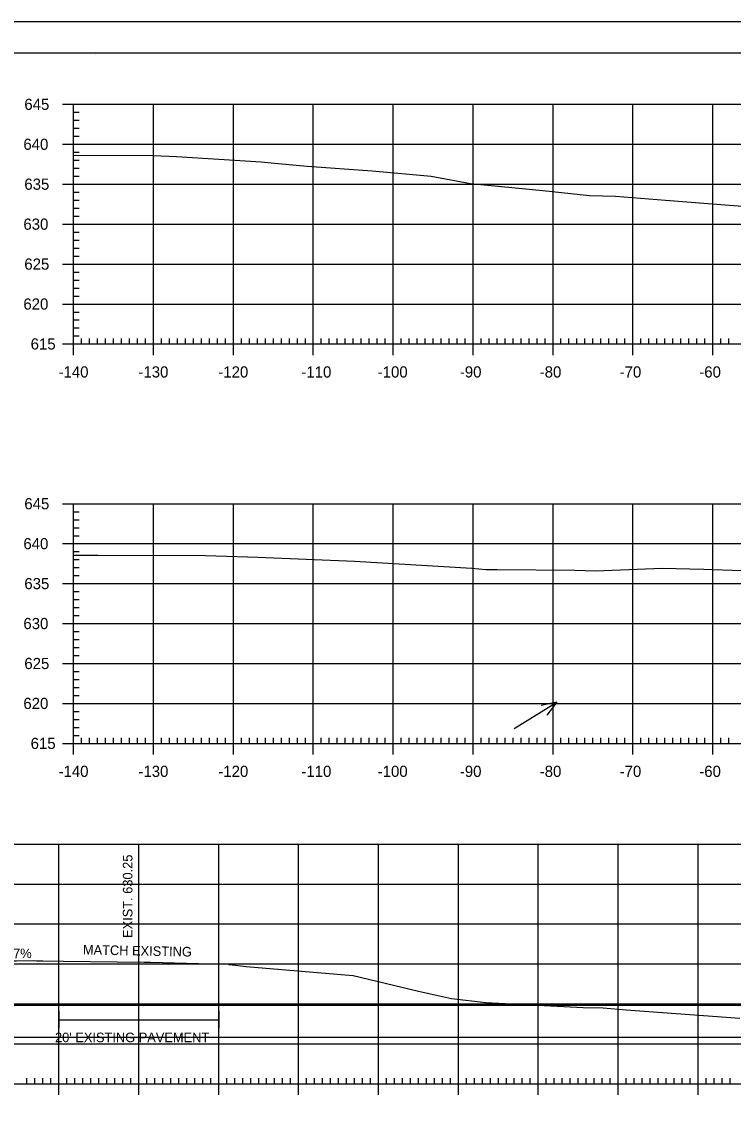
# Model space of a CAD drawing. Extents: x 1381471 to 1382703, y 370300 to 371487.
# Drawn here: x 1381990.1 to 1382079.2, y 370412.6 to 370547.6 of the extents above; entities that cross this region are included whole.
import ezdxf

# ---------------------------------------------------------------- set-up
doc = ezdxf.new("R2010")
doc.units = 0
for name, color, linetype in [('Level 16', 7, 'Continuous'), ('Level 18', 7, 'Continuous'), ('Level 21', 7, 'Continuous'), ('Level 22', 7, 'Continuous'), ('Level 26', 7, 'Continuous'), ('Level 4', 7, 'Continuous'), ('Level 40', 7, 'Continuous'), ('Level 41', 7, 'Continuous'), ('Level 42', 7, 'Continuous'), ('Level 45', 7, 'Continuous'), ('Level 6', 7, 'Continuous')]:
    doc.layers.add(name, color=color, linetype=linetype)

msp = doc.modelspace()

# ---------------------------------------------------------------- linework, layer by layer
at = {"layer": 'Level 16'}
for p, q in [((1381994.77, 370423.74), (1381994.77, 370421.61)), ((1382014.77, 370423.74), (1382014.77, 370421.61)), ((1381994.77, 370422.68), (1382014.77, 370422.68))]:
    msp.add_line(p, q, dxfattribs=at)
msp.add_lwpolyline([(1381986.4, 370430.03), (1381991.53, 370430.07), (1381991.98, 370430.06), (1381992.77, 370430.05)], dxfattribs=at)
at = {"layer": 'Level 18'}
msp.add_lwpolyline([(1381987.42, 370430.02), (1381991.53, 370430.07), (1381991.98, 370430.06), (1382005.44, 370429.9), (1382006.23, 370429.88), (1382012.23, 370429.71), (1382016, 370429.61), (1382016.04, 370429.6), (1382016.11, 370429.59), (1382018.19, 370429.34), (1382031.61, 370428.19), (1382039.79, 370426.26), (1382043.91, 370425.34), (1382048.19, 370424.85), (1382060.4, 370424.19), (1382062.89, 370424.17), (1382065.76, 370423.9), (1382080, 370422.87)], dxfattribs=at)
at = {"layer": 'Level 22'}
for p, q in [((1381864.77, 370444.66), (1382144.77, 370444.66)), ((1381994.77, 370414.66), (1381994.77, 370444.66)), ((1382004.77, 370414.66), (1382004.77, 370444.66)), ((1382014.77, 370414.66), (1382014.77, 370444.66)), ((1382024.77, 370414.66), (1382024.77, 370444.66)), ((1382034.77, 370414.66), (1382034.77, 370444.66)), ((1382044.77, 370414.66), (1382044.77, 370444.66)), ((1382054.77, 370414.66), (1382054.77, 370444.66)), ((1382064.77, 370414.66), (1382064.77, 370444.66)), ((1382074.77, 370414.66), (1382074.77, 370444.66)), ((1381864.77, 370439.66), (1382144.77, 370439.66)), ((1381864.77, 370434.66), (1382144.77, 370434.66)), ((1381864.77, 370429.66), (1382144.77, 370429.66)), ((1381864.77, 370424.66), (1382144.77, 370424.66)), ((1381864.77, 370419.66), (1382144.77, 370419.66)), ((1381864.77, 370414.66), (1382144.77, 370414.66))]:
    msp.add_line(p, q, dxfattribs=at)
at = {"layer": 'Level 26'}
msp.add_line((1381834.37, 370547.63), (1382167.7, 370547.63), dxfattribs=at)
for points in [[(1381834.36, 370547.63), (1382167.7, 370547.63), (1382167.7, 370334.29), (1381834.36, 370334.29)], [(1382080.69, 370543.73), (1382100.31, 370543.73), (1382100.31, 370533.85), (1382116.42, 370533.85), (1382139.62, 370533.85), (1382139.62, 370501.18), (1382162.83, 370501.18), (1382162.95, 370338.27), (1381846.77, 370338.27), (1381846.77, 370543.73)]]:
    msp.add_lwpolyline(points, close=True, dxfattribs=at)
at = {"layer": 'Level 4'}
for p, q in [((1381994.77, 370413.26), (1381994.77, 370416.06)), ((1382004.77, 370413.26), (1382004.77, 370416.06)), ((1382014.77, 370413.26), (1382014.77, 370416.06)), ((1382024.77, 370413.26), (1382024.77, 370416.06)), ((1382034.77, 370413.26), (1382034.77, 370416.06)), ((1382044.77, 370413.26), (1382044.77, 370416.06)), ((1382054.77, 370413.26), (1382054.77, 370416.06)), ((1382064.77, 370413.26), (1382064.77, 370416.06)), ((1382074.77, 370413.26), (1382074.77, 370416.06)), ((1381864.77, 370414.66), (1382144.77, 370414.66)), ((1381990.77, 370414.66), (1381990.77, 370415.36)), ((1381991.77, 370414.66), (1381991.77, 370415.36)), ((1381992.77, 370414.66), (1381992.77, 370415.36)), ((1381993.77, 370414.66), (1381993.77, 370415.36)), ((1381995.77, 370414.66), (1381995.77, 370415.36)), ((1381996.77, 370414.66), (1381996.77, 370415.36)), ((1381997.77, 370414.66), (1381997.77, 370415.36)), ((1381998.77, 370414.66), (1381998.77, 370415.36)), ((1381999.77, 370414.66), (1381999.77, 370415.36)), ((1382000.77, 370414.66), (1382000.77, 370415.36)), ((1382001.77, 370414.66), (1382001.77, 370415.36)), ((1382002.77, 370414.66), (1382002.77, 370415.36)), ((1382003.77, 370414.66), (1382003.77, 370415.36)), ((1382005.77, 370414.66), (1382005.77, 370415.36)), ((1382006.77, 370414.66), (1382006.77, 370415.36)), ((1382007.77, 370414.66), (1382007.77, 370415.36)), ((1382008.77, 370414.66), (1382008.77, 370415.36)), ((1382009.77, 370414.66), (1382009.77, 370415.36)), ((1382010.77, 370414.66), (1382010.77, 370415.36)), ((1382011.77, 370414.66), (1382011.77, 370415.36)), ((1382012.77, 370414.66), (1382012.77, 370415.36)), ((1382013.77, 370414.66), (1382013.77, 370415.36)), ((1382015.77, 370414.66), (1382015.77, 370415.36)), ((1382016.77, 370414.66), (1382016.77, 370415.36)), ((1382017.77, 370414.66), (1382017.77, 370415.36)), ((1382018.77, 370414.66), (1382018.77, 370415.36)), ((1382019.77, 370414.66), (1382019.77, 370415.36)), ((1382020.77, 370414.66), (1382020.77, 370415.36)), ((1382021.77, 370414.66), (1382021.77, 370415.36)), ((1382022.77, 370414.66), (1382022.77, 370415.36)), ((1382023.77, 370414.66), (1382023.77, 370415.36)), ((1382025.77, 370414.66), (1382025.77, 370415.36)), ((1382026.77, 370414.66), (1382026.77, 370415.36)), ((1382027.77, 370414.66), (1382027.77, 370415.36)), ((1382028.77, 370414.66), (1382028.77, 370415.36)), ((1382029.77, 370414.66), (1382029.77, 370415.36)), ((1382030.77, 370414.66), (1382030.77, 370415.36)), ((1382031.77, 370414.66), (1382031.77, 370415.36)), ((1382032.77, 370414.66), (1382032.77, 370415.36)), ((1382033.77, 370414.66), (1382033.77, 370415.36)), ((1382035.77, 370414.66), (1382035.77, 370415.36)), ((1382036.77, 370414.66), (1382036.77, 370415.36)), ((1382037.77, 370414.66), (1382037.77, 370415.36)), ((1382038.77, 370414.66), (1382038.77, 370415.36)), ((1382039.77, 370414.66), (1382039.77, 370415.36)), ((1382040.77, 370414.66), (1382040.77, 370415.36)), ((1382041.77, 370414.66), (1382041.77, 370415.36)), ((1382042.77, 370414.66), (1382042.77, 370415.36)), ((1382043.77, 370414.66), (1382043.77, 370415.36)), ((1382045.77, 370414.66), (1382045.77, 370415.36)), ((1382046.77, 370414.66), (1382046.77, 370415.36)), ((1382047.77, 370414.66), (1382047.77, 370415.36)), ((1382048.77, 370414.66), (1382048.77, 370415.36)), ((1382049.77, 370414.66), (1382049.77, 370415.36)), ((1382050.77, 370414.66), (1382050.77, 370415.36)), ((1382051.77, 370414.66), (1382051.77, 370415.36)), ((1382052.77, 370414.66), (1382052.77, 370415.36)), ((1382053.77, 370414.66), (1382053.77, 370415.36)), ((1382055.77, 370414.66), (1382055.77, 370415.36)), ((1382056.77, 370414.66), (1382056.77, 370415.36)), ((1382057.77, 370414.66), (1382057.77, 370415.36)), ((1382058.77, 370414.66), (1382058.77, 370415.36)), ((1382059.77, 370414.66), (1382059.77, 370415.36)), ((1382060.77, 370414.66), (1382060.77, 370415.36)), ((1382061.77, 370414.66), (1382061.77, 370415.36)), ((1382062.77, 370414.66), (1382062.77, 370415.36)), ((1382063.77, 370414.66), (1382063.77, 370415.36)), ((1382065.77, 370414.66), (1382065.77, 370415.36)), ((1382066.77, 370414.66), (1382066.77, 370415.36)), ((1382067.77, 370414.66), (1382067.77, 370415.36)), ((1382068.77, 370414.66), (1382068.77, 370415.36)), ((1382069.77, 370414.66), (1382069.77, 370415.36)), ((1382070.77, 370414.66), (1382070.77, 370415.36)), ((1382071.77, 370414.66), (1382071.77, 370415.36)), ((1382072.77, 370414.66), (1382072.77, 370415.36)), ((1382073.77, 370414.66), (1382073.77, 370415.36)), ((1382075.77, 370414.66), (1382075.77, 370415.36)), ((1382076.77, 370414.66), (1382076.77, 370415.36)), ((1382077.77, 370414.66), (1382077.77, 370415.36)), ((1382078.77, 370414.66), (1382078.77, 370415.36))]:
    msp.add_line(p, q, dxfattribs=at)
at = {"layer": 'Level 40'}
for p, q in [((1382051.77, 370459.12), (1382057.11, 370462.42)), ((1382057.11, 370462.42), (1382055.11, 370462.01)), ((1382057.11, 370462.42), (1382055.85, 370460.82))]:
    msp.add_line(p, q, dxfattribs=at)
at = {"layer": 'Level 45'}
for p, q in [((1381995.21, 370537.27), (1381998.01, 370537.27)), ((1381996.61, 370537.27), (1382276.61, 370537.27)), ((1381996.61, 370507.27), (1381996.61, 370537.27)), ((1381996.61, 370507.27), (1381996.61, 370537.27)), ((1381996.61, 370536.27), (1381997.31, 370536.27)), ((1382006.61, 370507.27), (1382006.61, 370537.27)), ((1382016.61, 370507.27), (1382016.61, 370537.27)), ((1382026.61, 370507.27), (1382026.61, 370537.27)), ((1382036.61, 370507.27), (1382036.61, 370537.27)), ((1382046.61, 370507.27), (1382046.61, 370537.27)), ((1382056.61, 370507.27), (1382056.61, 370537.27)), ((1382066.61, 370507.27), (1382066.61, 370537.27)), ((1382076.61, 370507.27), (1382076.61, 370537.27)), ((1381996.61, 370535.27), (1381997.31, 370535.27)), ((1381996.61, 370534.27), (1381997.31, 370534.27)), ((1381995.21, 370532.27), (1381998.01, 370532.27)), ((1381996.61, 370533.27), (1381997.31, 370533.27)), ((1381996.61, 370532.27), (1382276.61, 370532.27)), ((1381996.61, 370531.27), (1381997.31, 370531.27)), ((1381996.61, 370530.27), (1381997.31, 370530.27)), ((1381996.61, 370529.27), (1381997.31, 370529.27)), ((1381996.61, 370528.27), (1381997.31, 370528.27)), ((1381995.21, 370527.27), (1381998.01, 370527.27)), ((1381996.61, 370527.27), (1382276.61, 370527.27)), ((1381996.61, 370526.27), (1381997.31, 370526.27)), ((1381996.61, 370525.27), (1381997.31, 370525.27)), ((1381996.61, 370524.27), (1381997.31, 370524.27)), ((1381996.61, 370523.27), (1381997.31, 370523.27)), ((1381995.21, 370522.27), (1381998.01, 370522.27)), ((1381996.61, 370522.27), (1382276.61, 370522.27)), ((1381996.61, 370521.27), (1381997.31, 370521.27)), ((1381996.61, 370520.27), (1381997.31, 370520.27)), ((1381996.61, 370519.27), (1381997.31, 370519.27)), ((1381996.61, 370518.27), (1381997.31, 370518.27)), ((1381995.21, 370517.27), (1381998.01, 370517.27)), ((1381996.61, 370517.27), (1382276.61, 370517.27)), ((1381996.61, 370516.27), (1381997.31, 370516.27)), ((1381996.61, 370515.27), (1381997.31, 370515.27)), ((1381996.61, 370514.27), (1381997.31, 370514.27)), ((1381996.61, 370513.27), (1381997.31, 370513.27)), ((1381995.21, 370512.27), (1381998.01, 370512.27)), ((1381996.61, 370512.27), (1382276.61, 370512.27)), ((1381996.61, 370511.27), (1381997.31, 370511.27)), ((1381996.61, 370510.27), (1381997.31, 370510.27)), ((1381996.61, 370509.27), (1381997.31, 370509.27)), ((1381996.61, 370505.87), (1381996.61, 370508.67)), ((1381996.61, 370508.27), (1381997.31, 370508.27)), ((1381997.61, 370507.27), (1381997.61, 370507.97)), ((1381998.61, 370507.27), (1381998.61, 370507.97)), ((1381999.61, 370507.27), (1381999.61, 370507.97)), ((1382000.61, 370507.27), (1382000.61, 370507.97)), ((1382001.61, 370507.27), (1382001.61, 370507.97)), ((1382002.61, 370507.27), (1382002.61, 370507.97)), ((1382003.61, 370507.27), (1382003.61, 370507.97)), ((1382004.61, 370507.27), (1382004.61, 370507.97)), ((1382005.61, 370507.27), (1382005.61, 370507.97)), ((1382006.61, 370505.87), (1382006.61, 370508.67)), ((1382007.61, 370507.27), (1382007.61, 370507.97)), ((1382008.61, 370507.27), (1382008.61, 370507.97)), ((1382009.61, 370507.27), (1382009.61, 370507.97)), ((1382010.61, 370507.27), (1382010.61, 370507.97)), ((1382011.61, 370507.27), (1382011.61, 370507.97)), ((1382012.61, 370507.27), (1382012.61, 370507.97)), ((1382013.61, 370507.27), (1382013.61, 370507.97)), ((1382014.61, 370507.27), (1382014.61, 370507.97)), ((1382015.61, 370507.27), (1382015.61, 370507.97)), ((1382016.61, 370505.87), (1382016.61, 370508.67)), ((1382017.61, 370507.27), (1382017.61, 370507.97)), ((1382018.61, 370507.27), (1382018.61, 370507.97)), ((1382019.61, 370507.27), (1382019.61, 370507.97)), ((1382020.61, 370507.27), (1382020.61, 370507.97)), ((1382021.61, 370507.27), (1382021.61, 370507.97)), ((1382022.61, 370507.27), (1382022.61, 370507.97)), ((1382023.61, 370507.27), (1382023.61, 370507.97)), ((1382024.61, 370507.27), (1382024.61, 370507.97)), ((1382025.61, 370507.27), (1382025.61, 370507.97)), ((1382026.61, 370505.87), (1382026.61, 370508.67)), ((1382027.61, 370507.27), (1382027.61, 370507.97)), ((1382028.61, 370507.27), (1382028.61, 370507.97)), ((1382029.61, 370507.27), (1382029.61, 370507.97)), ((1382030.61, 370507.27), (1382030.61, 370507.97)), ((1382031.61, 370507.27), (1382031.61, 370507.97)), ((1382032.61, 370507.27), (1382032.61, 370507.97)), ((1382033.61, 370507.27), (1382033.61, 370507.97)), ((1382034.61, 370507.27), (1382034.61, 370507.97)), ((1382035.61, 370507.27), (1382035.61, 370507.97)), ((1382036.61, 370505.87), (1382036.61, 370508.67)), ((1382037.61, 370507.27), (1382037.61, 370507.97)), ((1382038.61, 370507.27), (1382038.61, 370507.97)), ((1382039.61, 370507.27), (1382039.61, 370507.97)), ((1382040.61, 370507.27), (1382040.61, 370507.97)), ((1382041.61, 370507.27), (1382041.61, 370507.97)), ((1382042.61, 370507.27), (1382042.61, 370507.97)), ((1382043.61, 370507.27), (1382043.61, 370507.97)), ((1382044.61, 370507.27), (1382044.61, 370507.97)), ((1382045.61, 370507.27), (1382045.61, 370507.97)), ((1382046.61, 370505.87), (1382046.61, 370508.67)), ((1382047.61, 370507.27), (1382047.61, 370507.97)), ((1382048.61, 370507.27), (1382048.61, 370507.97)), ((1382049.61, 370507.27), (1382049.61, 370507.97)), ((1382050.61, 370507.27), (1382050.61, 370507.97)), ((1382051.61, 370507.27), (1382051.61, 370507.97)), ((1382052.61, 370507.27), (1382052.61, 370507.97)), ((1382053.61, 370507.27), (1382053.61, 370507.97)), ((1382054.61, 370507.27), (1382054.61, 370507.97)), ((1382055.61, 370507.27), (1382055.61, 370507.97)), ((1382056.61, 370505.87), (1382056.61, 370508.67)), ((1382057.61, 370507.27), (1382057.61, 370507.97)), ((1382058.61, 370507.27), (1382058.61, 370507.97)), ((1382059.61, 370507.27), (1382059.61, 370507.97)), ((1382060.61, 370507.27), (1382060.61, 370507.97)), ((1382061.61, 370507.27), (1382061.61, 370507.97)), ((1382062.61, 370507.27), (1382062.61, 370507.97)), ((1382063.61, 370507.27), (1382063.61, 370507.97)), ((1382064.61, 370507.27), (1382064.61, 370507.97)), ((1382065.61, 370507.27), (1382065.61, 370507.97)), ((1382066.61, 370505.87), (1382066.61, 370508.67)), ((1382067.61, 370507.27), (1382067.61, 370507.97)), ((1382068.61, 370507.27), (1382068.61, 370507.97)), ((1382069.61, 370507.27), (1382069.61, 370507.97)), ((1382070.61, 370507.27), (1382070.61, 370507.97)), ((1382071.61, 370507.27), (1382071.61, 370507.97)), ((1382072.61, 370507.27), (1382072.61, 370507.97)), ((1382073.61, 370507.27), (1382073.61, 370507.97)), ((1382074.61, 370507.27), (1382074.61, 370507.97)), ((1382075.61, 370507.27), (1382075.61, 370507.97)), ((1382076.61, 370505.87), (1382076.61, 370508.67)), ((1382077.61, 370507.27), (1382077.61, 370507.97)), ((1382078.61, 370507.27), (1382078.61, 370507.97)), ((1381995.21, 370507.27), (1381998.01, 370507.27)), ((1381996.61, 370507.27), (1382276.61, 370507.27)), ((1381996.61, 370507.27), (1382276.61, 370507.27)), ((1381995.21, 370487.27), (1381998.01, 370487.27)), ((1381996.61, 370487.27), (1382276.61, 370487.27)), ((1381996.61, 370457.27), (1381996.61, 370487.27)), ((1381996.61, 370457.27), (1381996.61, 370487.27)), ((1381996.61, 370486.27), (1381997.31, 370486.27)), ((1382006.61, 370457.27), (1382006.61, 370487.27)), ((1382016.61, 370457.27), (1382016.61, 370487.27)), ((1382026.61, 370457.27), (1382026.61, 370487.27)), ((1382036.61, 370457.27), (1382036.61, 370487.27)), ((1382046.61, 370457.27), (1382046.61, 370487.27)), ((1382056.61, 370457.27), (1382056.61, 370487.27)), ((1382066.61, 370457.27), (1382066.61, 370487.27)), ((1382076.61, 370457.27), (1382076.61, 370487.27)), ((1381996.61, 370485.27), (1381997.31, 370485.27)), ((1381996.61, 370484.27), (1381997.31, 370484.27)), ((1381995.21, 370482.27), (1381998.01, 370482.27)), ((1381996.61, 370483.27), (1381997.31, 370483.27)), ((1381996.61, 370482.27), (1382276.61, 370482.27)), ((1381996.61, 370481.27), (1381997.31, 370481.27)), ((1381996.61, 370480.27), (1381997.31, 370480.27)), ((1381996.61, 370479.27), (1381997.31, 370479.27)), ((1381996.61, 370478.27), (1381997.31, 370478.27)), ((1381995.21, 370477.27), (1381998.01, 370477.27)), ((1381996.61, 370477.27), (1382276.61, 370477.27)), ((1381996.61, 370476.27), (1381997.31, 370476.27)), ((1381996.61, 370475.27), (1381997.31, 370475.27)), ((1381996.61, 370474.27), (1381997.31, 370474.27)), ((1381996.61, 370473.27), (1381997.31, 370473.27)), ((1381995.21, 370472.27), (1381998.01, 370472.27)), ((1381996.61, 370472.27), (1382276.61, 370472.27)), ((1381996.61, 370471.27), (1381997.31, 370471.27)), ((1381996.61, 370470.27), (1381997.31, 370470.27)), ((1381996.61, 370469.27), (1381997.31, 370469.27)), ((1381996.61, 370468.27), (1381997.31, 370468.27)), ((1381995.21, 370467.27), (1381998.01, 370467.27)), ((1381996.61, 370467.27), (1382276.61, 370467.27)), ((1381996.61, 370466.27), (1381997.31, 370466.27)), ((1381996.61, 370465.27), (1381997.31, 370465.27)), ((1381996.61, 370464.27), (1381997.31, 370464.27)), ((1381996.61, 370463.27), (1381997.31, 370463.27)), ((1381995.21, 370462.27), (1381998.01, 370462.27)), ((1381996.61, 370462.27), (1382276.61, 370462.27)), ((1381996.61, 370461.27), (1381997.31, 370461.27)), ((1381996.61, 370460.27), (1381997.31, 370460.27)), ((1381996.61, 370459.27), (1381997.31, 370459.27)), ((1381996.61, 370455.87), (1381996.61, 370458.67)), ((1381996.61, 370458.27), (1381997.31, 370458.27)), ((1381997.61, 370457.27), (1381997.61, 370457.97)), ((1381998.61, 370457.27), (1381998.61, 370457.97)), ((1381999.61, 370457.27), (1381999.61, 370457.97)), ((1382000.61, 370457.27), (1382000.61, 370457.97)), ((1382001.61, 370457.27), (1382001.61, 370457.97)), ((1382002.61, 370457.27), (1382002.61, 370457.97)), ((1382003.61, 370457.27), (1382003.61, 370457.97)), ((1382004.61, 370457.27), (1382004.61, 370457.97)), ((1382005.61, 370457.27), (1382005.61, 370457.97)), ((1382006.61, 370455.87), (1382006.61, 370458.67)), ((1382007.61, 370457.27), (1382007.61, 370457.97)), ((1382008.61, 370457.27), (1382008.61, 370457.97)), ((1382009.61, 370457.27), (1382009.61, 370457.97)), ((1382010.61, 370457.27), (1382010.61, 370457.97)), ((1382011.61, 370457.27), (1382011.61, 370457.97)), ((1382012.61, 370457.27), (1382012.61, 370457.97)), ((1382013.61, 370457.27), (1382013.61, 370457.97)), ((1382014.61, 370457.27), (1382014.61, 370457.97)), ((1382015.61, 370457.27), (1382015.61, 370457.97)), ((1382016.61, 370455.87), (1382016.61, 370458.67)), ((1382017.61, 370457.27), (1382017.61, 370457.97)), ((1382018.61, 370457.27), (1382018.61, 370457.97)), ((1382019.61, 370457.27), (1382019.61, 370457.97)), ((1382020.61, 370457.27), (1382020.61, 370457.97)), ((1382021.61, 370457.27), (1382021.61, 370457.97)), ((1382022.61, 370457.27), (1382022.61, 370457.97)), ((1382023.61, 370457.27), (1382023.61, 370457.97)), ((1382024.61, 370457.27), (1382024.61, 370457.97)), ((1382025.61, 370457.27), (1382025.61, 370457.97)), ((1382026.61, 370455.87), (1382026.61, 370458.67)), ((1382027.61, 370457.27), (1382027.61, 370457.97)), ((1382028.61, 370457.27), (1382028.61, 370457.97)), ((1382029.61, 370457.27), (1382029.61, 370457.97)), ((1382030.61, 370457.27), (1382030.61, 370457.97)), ((1382031.61, 370457.27), (1382031.61, 370457.97)), ((1382032.61, 370457.27), (1382032.61, 370457.97)), ((1382033.61, 370457.27), (1382033.61, 370457.97)), ((1382034.61, 370457.27), (1382034.61, 370457.97)), ((1382035.61, 370457.27), (1382035.61, 370457.97)), ((1382036.61, 370455.87), (1382036.61, 370458.67)), ((1382037.61, 370457.27), (1382037.61, 370457.97)), ((1382038.61, 370457.27), (1382038.61, 370457.97)), ((1382039.61, 370457.27), (1382039.61, 370457.97)), ((1382040.61, 370457.27), (1382040.61, 370457.97)), ((1382041.61, 370457.27), (1382041.61, 370457.97)), ((1382042.61, 370457.27), (1382042.61, 370457.97)), ((1382043.61, 370457.27), (1382043.61, 370457.97)), ((1382044.61, 370457.27), (1382044.61, 370457.97)), ((1382045.61, 370457.27), (1382045.61, 370457.97)), ((1382046.61, 370455.87), (1382046.61, 370458.67)), ((1382047.61, 370457.27), (1382047.61, 370457.97)), ((1382048.61, 370457.27), (1382048.61, 370457.97)), ((1382049.61, 370457.27), (1382049.61, 370457.97)), ((1382050.61, 370457.27), (1382050.61, 370457.97)), ((1382051.61, 370457.27), (1382051.61, 370457.97)), ((1382052.61, 370457.27), (1382052.61, 370457.97)), ((1382053.61, 370457.27), (1382053.61, 370457.97)), ((1382054.61, 370457.27), (1382054.61, 370457.97)), ((1382055.61, 370457.27), (1382055.61, 370457.97)), ((1382056.61, 370455.87), (1382056.61, 370458.67)), ((1382057.61, 370457.27), (1382057.61, 370457.97)), ((1382058.61, 370457.27), (1382058.61, 370457.97)), ((1382059.61, 370457.27), (1382059.61, 370457.97)), ((1382060.61, 370457.27), (1382060.61, 370457.97)), ((1382061.61, 370457.27), (1382061.61, 370457.97)), ((1382062.61, 370457.27), (1382062.61, 370457.97)), ((1382063.61, 370457.27), (1382063.61, 370457.97)), ((1382064.61, 370457.27), (1382064.61, 370457.97)), ((1382065.61, 370457.27), (1382065.61, 370457.97)), ((1382066.61, 370455.87), (1382066.61, 370458.67)), ((1382067.61, 370457.27), (1382067.61, 370457.97)), ((1382068.61, 370457.27), (1382068.61, 370457.97)), ((1382069.61, 370457.27), (1382069.61, 370457.97)), ((1382070.61, 370457.27), (1382070.61, 370457.97)), ((1382071.61, 370457.27), (1382071.61, 370457.97)), ((1382072.61, 370457.27), (1382072.61, 370457.97)), ((1382073.61, 370457.27), (1382073.61, 370457.97)), ((1382074.61, 370457.27), (1382074.61, 370457.97)), ((1382075.61, 370457.27), (1382075.61, 370457.97)), ((1382076.61, 370455.87), (1382076.61, 370458.67)), ((1382077.61, 370457.27), (1382077.61, 370457.97)), ((1382078.61, 370457.27), (1382078.61, 370457.97)), ((1381995.21, 370457.27), (1381998.01, 370457.27)), ((1381996.61, 370457.27), (1382276.61, 370457.27)), ((1381996.61, 370457.27), (1382276.61, 370457.27)), ((1382294.79, 370424.44), (1381978.61, 370424.44)), ((1381966.21, 370420.47), (1382299.55, 370420.47))]:
    msp.add_line(p, q, dxfattribs=at)
for points in [[(1381966.21, 370633.8), (1382299.55, 370633.8), (1382299.55, 370420.46), (1381966.21, 370420.46)], [(1382212.53, 370629.9), (1382232.15, 370629.9), (1382232.15, 370620.02), (1382248.27, 370620.02), (1382271.46, 370620.02), (1382271.46, 370595.69), (1382294.79, 370595.69), (1382294.79, 370424.44), (1381978.61, 370424.44), (1381978.61, 370629.9)]]:
    msp.add_lwpolyline(points, close=True, dxfattribs=at)
for points in [[(1381996.61, 370530.89), (1382006.55, 370530.88), (1382009.5, 370530.74), (1382020.08, 370530.06), (1382021.73, 370529.9), (1382025.83, 370529.54), (1382033.97, 370528.95), (1382041.36, 370528.28), (1382046.29, 370527.36), (1382055.35, 370526.48), (1382061.16, 370525.85), (1382064.43, 370525.77), (1382070.71, 370525.28), (1382081.39, 370524.45)], [(1381996.61, 370480.84), (1381998.39, 370480.84), (1381999.37, 370480.83), (1381999.62, 370480.84), (1382013.12, 370480.8), (1382019.65, 370480.58), (1382031.77, 370480.08), (1382046.45, 370479.2), (1382048.21, 370479.02), (1382049.64, 370479.02), (1382059.36, 370478.96), (1382061.92, 370478.88), (1382070.27, 370479.19), (1382075.49, 370479.07), (1382080.2, 370478.93)]]:
    msp.add_lwpolyline(points, dxfattribs=at)
at = {"layer": 'Level 6'}
for p, q in [((1381846.77, 370543.73), (1382162.95, 370543.73)), ((1381999.29, 370543.47), (1381999.29, 370543.47)), ((1381999.29, 370543.47), (1381999.29, 370543.47))]:
    msp.add_line(p, q, dxfattribs=at)

# ---------------------------------------------------------------- texts
at = {"layer": 'Level 21'}
msp.add_text("20' EXISTING PAVEMENT", height=1.2, dxfattribs=at).set_placement((1381994.28, 370419.86))
at = {"layer": 'Level 41'}
for s, rotation, p in [('EXIST. 630.25', 90, (1382003.97, 370432.91)), ('0.87%', 0.4984, (1381986.81, 370430.35))]:
    msp.add_text(s, height=1.2, rotation=rotation, dxfattribs=at).set_placement(p)
at = {"layer": 'Level 42'}
msp.add_text('MATCH EXISTING', height=1.2, rotation=358.8542, dxfattribs=at).set_placement((1381997.76, 370430.85))
at = {"layer": 'Level 45'}
for s, p in [('645', (1381990.44, 370536.57)), ('640', (1381990.32, 370531.57)), ('635', (1381990.44, 370526.57)), ('630', (1381990.32, 370521.57)), ('625', (1381990.44, 370516.57)), ('620', (1381990.32, 370511.57)), ('615', (1381991.23, 370506.57)), ('-140', (1381994.72, 370503.07)), ('-130', (1382004.72, 370503.07)), ('-120', (1382014.72, 370503.07)), ('-110', (1382025.12, 370503.07)), ('-100', (1382034.67, 370503.07)), ('-90', (1382044.95, 370503.07)), ('-80', (1382054.95, 370503.07)), ('-70', (1382064.95, 370503.07)), ('-60', (1382074.92, 370503.07)), ('645', (1381990.44, 370486.57)), ('640', (1381990.32, 370481.57)), ('635', (1381990.44, 370476.57)), ('630', (1381990.32, 370471.57)), ('625', (1381990.44, 370466.57)), ('620', (1381990.32, 370461.57)), ('615', (1381991.23, 370456.57)), ('-140', (1381994.72, 370453.07)), ('-130', (1382004.72, 370453.07)), ('-120', (1382014.72, 370453.07)), ('-110', (1382025.12, 370453.07)), ('-100', (1382034.67, 370453.07)), ('-90', (1382044.95, 370453.07)), ('-80', (1382054.95, 370453.07)), ('-70', (1382064.95, 370453.07)), ('-60', (1382074.92, 370453.07))]:
    msp.add_text(s, height=1.4, dxfattribs=at).set_placement(p)

doc.saveas('drawing.dxf')
